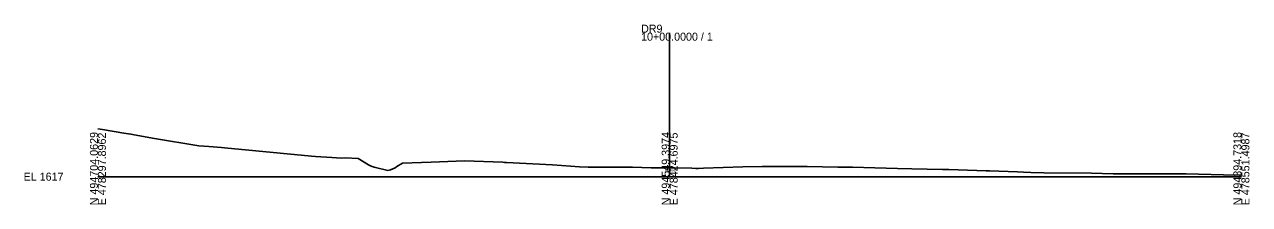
# Model space of a CAD drawing. Extents: x -26 to 403, y -10 to 1525.
# Drawn here: x -25.7 to 402.8, y -9.7 to 53.1 of the extents above; entities that cross this region are included whole.
import ezdxf

# ---------------------------------------------------------------- set-up
doc = ezdxf.new("R2010")
doc.units = 0
for name, color, linetype in [('Exist Cross Section Cell', 7, 'Continuous'), ('Exist XS Center Line Elevation Label', 7, 'Continuous'), ('Exist XS Ground Line', 7, 'Continuous'), ('Scratch_Level_5', 7, 'Continuous')]:
    doc.layers.add(name, color=color, linetype=linetype)

msp = doc.modelspace()

# ---------------------------------------------------------------- linework, layer by layer
at = {"layer": 'Exist Cross Section Cell'}
for p, q in [((200, 0), (200, 50.28)), ((0, 0), (200, 0)), ((200, 0), (400, 0))]:
    msp.add_line(p, q, dxfattribs=at)
at = {"layer": 'Exist XS Ground Line'}
msp.add_lwpolyline([(0, 16.76), (1.57, 16.48), (9.05, 15.25), (11.51, 14.87), (12.69, 14.63), (19.73, 13.36), (35.29, 10.83), (38.76, 10.54), (43.18, 10.16), (44.26, 10.08), (74.74, 7.19), (76.15, 7.05), (81.77, 6.71), (85.12, 6.51), (86.47, 6.56), (91.05, 6.32), (94.66, 4.18), (95.57, 3.62), (96.61, 3.31), (101.46, 2.17), (102.34, 2.41), (103.96, 3.15), (104.52, 3.61), (106.53, 4.73), (113.2, 4.99), (116.54, 5.02), (128.28, 5.58), (141.69, 5.08), (142.26, 5.01), (142.97, 4.95), (159.03, 4.1), (168.48, 3.46), (171.44, 3.28), (187.04, 3.29), (193.58, 3.08), (197.45, 3.07), (200, 3.06), (201.75, 3.05), (207.77, 2.93), (209.17, 2.85), (210.07, 2.91), (211.86, 2.95), (225.58, 3.43), (232.37, 3.55), (232.95, 3.55), (235.61, 3.55), (245.89, 3.52), (248.15, 3.54), (258.82, 3.3), (263.92, 3.27), (271.75, 3.12), (279.7, 2.82), (284.69, 2.76), (295.47, 2.51), (297.62, 2.46), (307.4, 2.18), (310.7, 2.09), (311.9, 2.04), (321.71, 1.68), (323.79, 1.55), (326.34, 1.51), (330.88, 1.36), (347.6, 1.21), (355.17, 1.04), (363.69, 1.02), (377.62, 0.94), (380.67, 0.94), (393.71, 0.69), (400, 0.55)], dxfattribs=at)
at = {"layer": 'Scratch_Level_5'}
msp.add_lwpolyline([(0, 16.76), (1.57, 16.48), (9.05, 15.25), (11.51, 14.87), (12.69, 14.63), (19.73, 13.36), (35.29, 10.83), (38.76, 10.54), (43.18, 10.16), (44.26, 10.08), (74.74, 7.19), (76.15, 7.05), (81.77, 6.71), (85.12, 6.51), (86.47, 6.56), (91.05, 6.32), (94.66, 4.18), (95.57, 3.62), (96.61, 3.31), (101.46, 2.17), (102.34, 2.41), (103.96, 3.15), (104.52, 3.61), (106.53, 4.73), (113.2, 4.99), (116.54, 5.02), (128.28, 5.58), (141.69, 5.08), (142.26, 5.01), (142.97, 4.95), (159.03, 4.1), (168.48, 3.46), (171.44, 3.28), (187.04, 3.29), (193.58, 3.08), (197.45, 3.07), (200, 3.06), (201.75, 3.05), (207.77, 2.93), (209.17, 2.85), (210.07, 2.91), (211.86, 2.95), (225.58, 3.43), (232.37, 3.55), (232.95, 3.55), (235.61, 3.55), (245.89, 3.52), (248.15, 3.54), (258.82, 3.3), (263.92, 3.27), (271.75, 3.12), (279.7, 2.82), (284.69, 2.76), (295.47, 2.51), (297.62, 2.46), (307.4, 2.18), (310.7, 2.09), (311.9, 2.04), (321.71, 1.68), (323.79, 1.55), (326.34, 1.51), (330.88, 1.36), (347.6, 1.21), (355.17, 1.04), (363.69, 1.02), (377.62, 0.94), (380.67, 0.94), (393.71, 0.69), (400, 0.55)], dxfattribs=at)

# ---------------------------------------------------------------- texts
at = {"layer": 'Exist Cross Section Cell'}
for s, p in [('DR9', (190, 50.28)), ('10+00.0000 / 1', (190, 47.48)), ('EL 1617', (-26, -1.4))]:
    msp.add_text(s, height=2.8, dxfattribs=at).set_placement(p)
for s, p in [('N 494704.0629', (0, -10)), ('E 478297.8962', (2.8, -10)), ('N 494549.3974', (200, -10)), ('E 478424.6975', (202.8, -10)), ('N 494394.7318', (400, -10)), ('E 478551.4987', (402.8, -10))]:
    msp.add_text(s, height=2.8, rotation=90, dxfattribs=at).set_placement(p)
at = {"layer": 'Exist XS Center Line Elevation Label'}
msp.add_text('1620.06', height=0.75, dxfattribs=at).set_placement((198.23, 1.81))

doc.saveas('drawing.dxf')
